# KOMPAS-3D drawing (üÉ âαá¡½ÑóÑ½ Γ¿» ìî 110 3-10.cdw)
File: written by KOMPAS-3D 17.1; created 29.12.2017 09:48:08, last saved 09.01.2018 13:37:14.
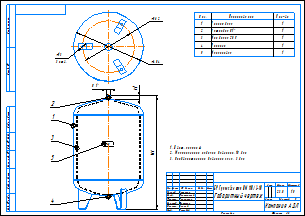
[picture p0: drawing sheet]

Sheet 1: A3, landscape, title-block layout from C:\Лощинин\GRAPHIC.LYT style 1

Title block, sheet 1: name: БР Гранлевел тип НМ 110/3-10 / Габаритный чертеж; mass: 23,8; sheets: 1; sheet format: A3; stored path: \\Fsk1\files\АП\20_PKO\02_Насосное направление\Разработка\04_Проекты разные\Баки\КД действующая\Баки Flexcon R\Компас\Чертежи\БР Гранлевел тип НМ 110 1,5-6.cdw; drawn by: Лощинин; checked by: Хантимеров

Views: Проекционный вид 3
Referenced files in \\Fsk1\files\АП\20_PKO\02_Насосное направление\Разработка\04_Проекты разные\Баки\КД действующая\Баки Flexcon R\Компас\: 110 литров.a3d, 16116_Flexcon_110_1-6.m3d
Referenced files in C:\Лощинин\: GRAPHIC.LYT
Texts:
  IvAn
  ADL
  Поз.
  Кол-во
  Корпус бака
  Мембрана SBR
  Патрубок G1"
  Ниппель
  Маркировка
  АДЛ
  БР Гранлевел тип НМ 110/1,5-6
  Цвет: красный
  Максимальное рабочее давление: 10 бар
  Предварительное давление газа: 3 бар
  ACAD_ISO03W100_RGB_223_127_255_SC_0.063_THICK_0.05
  ACAD_ISO03W100_RGB_223_127_255_SC_1_THICK_0.05
  Лит-Масса-Масштаб
  Материал-Предприятие
  Масштаб
  Изм.
  Лист
  № докум.
  Подп.
  Дата
  Лит.
  Разраб.
  Пров.
  Т.контр.
  Курлыкина
  Листов
  Нач.отд.
  Щетинин
  Н.контр.
  Долгов
  Утв.
  Рашидов
  Компания АДЛ
  Изменение
  Номер документа
  Подпись
  Обозначение документа
  Наименование изделия
  Масса изделия по ГОСТ 2.109-73
  Порядковый номер листа
  Общее количество листов в документе
  Характер работы, выполненной лицом, подписавшим документ
  Наименование или индекс предприятия, выпускающего документ
  Инв. № подл.
  Подп. и дата
  Взам. инв. №
  Инв. № дубл.
  Инвентарный номер подлинника по ГОСТ 2.501-68
  Подпись принявшего подлинник в отдел технической документации
  Инвентарный номер подлинника, взамен которого выпущен данный подлинник
  Инвентарный номер дубликата по ГОСТ 2.502-68
  Подпись принявшего дубликат в отдел технической документации
  Справ. №
  Перв. примен.
  Обозначение документа, взамен или на основании которого выпущен данный документ
  Обозначение документа, в котором впервые записан данный документ
  Подпись лица, копировавшего чертеж
  Обозначение формата листа
Dimensions and other numbers on the sheet: 1; 3; 2; 4; 5; 780; 21; 1:5; 23,8; 16116_Flexcon_110_1-6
